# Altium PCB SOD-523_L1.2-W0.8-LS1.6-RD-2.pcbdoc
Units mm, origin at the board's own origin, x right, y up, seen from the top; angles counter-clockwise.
Board outline 15.18 x 13.7 mm, 2 copper layers (Top Layer, Bottom Layer), stack 0 mm thick; 1 components, 0 nets, 2 pads, 0 vias.
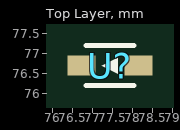
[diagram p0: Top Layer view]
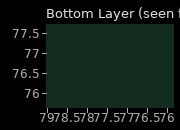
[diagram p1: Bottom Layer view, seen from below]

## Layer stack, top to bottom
Top Layer: signal copper (thickness not stored)
Bottom Layer: signal copper (thickness not stored)

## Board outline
85.029,69.85 69.85,69.85 69.85,83.55 85.029,83.55

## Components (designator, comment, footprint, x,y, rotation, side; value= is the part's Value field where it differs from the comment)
U? "" SOD-523_L1.2-W0.8-LS1.6-RD-2 77.429,76.7 r0 top

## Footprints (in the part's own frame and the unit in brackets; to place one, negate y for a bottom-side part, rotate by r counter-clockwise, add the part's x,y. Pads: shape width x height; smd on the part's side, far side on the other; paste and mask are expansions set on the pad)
SOD-523_L1.2-W0.8-LS1.6-RD-2 [mm]
  rect 0.7x0.5 smd: 1(-0.71,0) 2(0.71,0)
  silkscreen extent -0.6,-0.5 0.6,0.5

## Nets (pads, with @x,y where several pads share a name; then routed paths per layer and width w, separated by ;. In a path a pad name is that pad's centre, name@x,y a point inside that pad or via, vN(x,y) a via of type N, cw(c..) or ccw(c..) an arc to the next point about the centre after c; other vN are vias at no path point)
pads on no net: U?.1 U?.2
